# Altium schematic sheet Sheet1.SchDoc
size A4
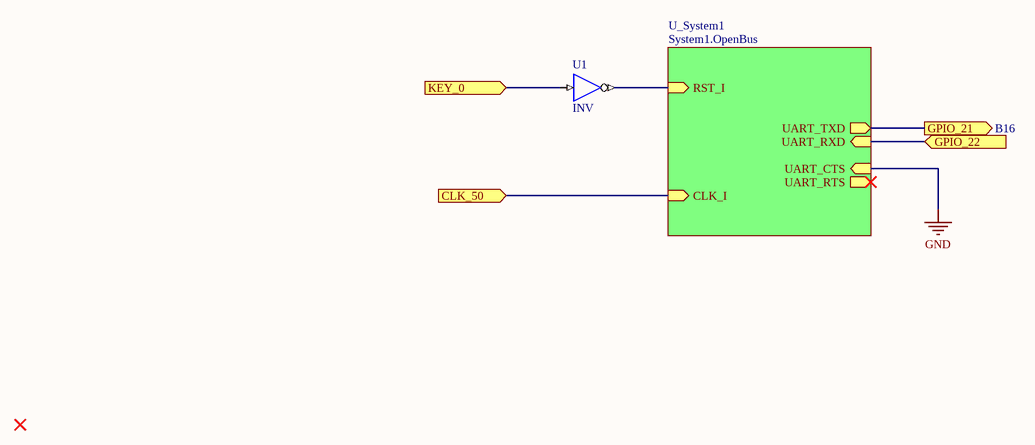
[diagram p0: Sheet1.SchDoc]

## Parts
U1  INV

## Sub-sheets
U_System1 = System1.OpenBus: UART_TXD (out), UART_RXD (in), UART_CTS (in), UART_RTS (out), RST_I (in), CLK_I (in)

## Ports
CLK_50 (in), GPIO_21 (out, see B16), GPIO_22 (in), KEY_0 (in)

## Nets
CLK_50: port CLK_50, sheet U_System1/CLK_I
GPIO_21: port GPIO_21, sheet U_System1/UART_TXD
GPIO_22: port GPIO_22, sheet U_System1/UART_RXD
KEY_0: U1.I ; port KEY_0
NetU1_O: U1.O ; sheet U_System1/RST_I

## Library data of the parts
U1 = INV: Inverter; FunctionalClass: Logic Primitive; ArchiveName: GENERIC; VHDLIB_SIM: GENERIC_LIB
